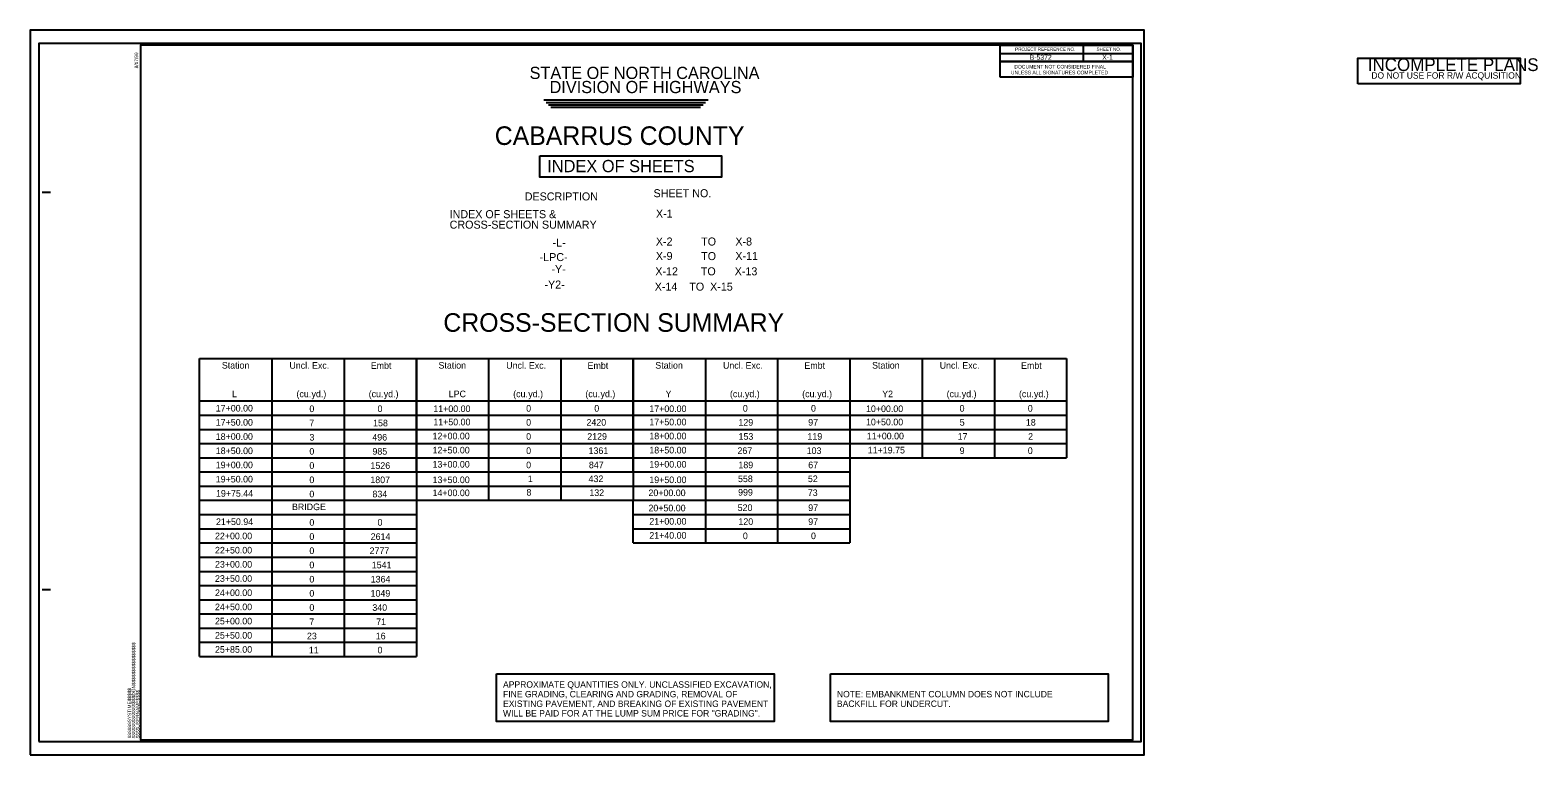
# Model space of a CAD drawing. Extents: x -16215 to -14848, y -1968 to -1311.
import ezdxf

# ---------------------------------------------------------------- set-up
doc = ezdxf.new("R2010")
doc.units = 0
for name, color, linetype in [('Default', 7, 'Continuous'), ('Old_Level_12', 7, 'Continuous'), ('Old_Level_40', 7, 'Continuous'), ('Old_Level_44', 7, 'Continuous'), ('Prop DSN Text', 7, 'Continuous'), ('Sheet Data Field CELL', 7, 'Continuous'), ('Sheet Plan CELL', 7, 'Continuous'), ('Sheet Plot Border Inside CELL', 7, 'Continuous'), ('Sheet Plot Border Outside CELL', 7, 'Continuous'), ('Sheet Sticker Exception Certification CELL', 7, 'Continuous'), ('Sheet Sticker Incomplete CELL', 7, 'Continuous')]:
    doc.layers.add(name, color=color, linetype=linetype)

msp = doc.modelspace()

# ---------------------------------------------------------------- linework, layer by layer
at = {"layer": 'Default'}
for points in [[(-15753.3, -1424.7), (-15588.5, -1424.7), (-15588.5, -1444), (-15753.3, -1443.9)], [(-15792.5, -1894.3), (-15540.6, -1894.3), (-15540.6, -1937.4), (-15792.5, -1937.4)], [(-15489.7, -1894.3), (-15237.8, -1894.3), (-15237.8, -1937.4), (-15489.7, -1937.4)]]:
    msp.add_lwpolyline(points, close=True, dxfattribs=at)
at = {"layer": 'Old_Level_12'}
for p, q in [((-15749.7, -1374), (-15600.6, -1374)), ((-15749.7, -1374), (-15600.6, -1374)), ((-15747.6, -1376.3), (-15602.9, -1376.3)), ((-15745.3, -1378.5), (-15605.2, -1378.5)), ((-15743.1, -1380.7), (-15607.5, -1380.7))]:
    msp.add_line(p, q, dxfattribs=at)
at = {"layer": 'Prop DSN Text'}
for p, q in [((-16061.8, -1608.3), (-15865.2, -1608.3)), ((-16061.8, -1878.6), (-16061.8, -1608.3)), ((-15996.2, -1608.3), (-15996.2, -1711.3)), ((-15930.7, -1608.3), (-15930.7, -1711.3)), ((-15865.2, -1608.3), (-15865.2, -1878.6)), ((-15865.2, -1608.3), (-15668.6, -1608.3)), ((-15865.2, -1711.3), (-15865.2, -1608.3)), ((-15799.7, -1608.3), (-15799.7, -1737)), ((-15734.2, -1608.3), (-15734.2, -1737)), ((-15668.6, -1608.3), (-15668.6, -1737)), ((-15668.6, -1608.3), (-15472.1, -1608.3)), ((-15668.6, -1711.3), (-15668.6, -1608.3)), ((-15603.1, -1608.3), (-15603.1, -1737)), ((-15537.6, -1608.3), (-15537.6, -1737)), ((-15472.1, -1608.3), (-15472.1, -1737)), ((-15472.1, -1608.3), (-15275.5, -1608.3)), ((-15406.6, -1608.3), (-15406.6, -1698.4)), ((-15341, -1608.3), (-15341, -1698.4)), ((-15275.5, -1608.3), (-15275.5, -1698.4)), ((-16061.8, -1646.9), (-15865.2, -1646.9)), ((-15996.2, -1646.6), (-15996.2, -1878.2)), ((-15930.7, -1646.6), (-15930.7, -1878.2)), ((-15865.2, -1646.9), (-15668.6, -1646.9)), ((-15668.6, -1646.9), (-15472.1, -1646.9)), ((-15472.1, -1646.9), (-15275.5, -1646.9)), ((-16061.8, -1659.8), (-15865.2, -1659.8)), ((-15865.2, -1659.8), (-15668.6, -1659.8)), ((-15668.6, -1659.8), (-15472.1, -1659.8)), ((-15472.1, -1659.8), (-15275.5, -1659.8)), ((-16061.8, -1672.7), (-15865.2, -1672.7)), ((-15865.2, -1672.7), (-15668.6, -1672.7)), ((-15668.6, -1672.7), (-15472.1, -1672.7)), ((-15472.1, -1672.7), (-15275.5, -1672.7)), ((-16061.8, -1685.5), (-15865.2, -1685.5)), ((-15865.2, -1685.5), (-15668.6, -1685.5)), ((-15668.6, -1685.5), (-15472.1, -1685.5)), ((-15472.1, -1685.5), (-15275.5, -1685.5)), ((-16061.8, -1698.4), (-15865.2, -1698.4)), ((-15865.2, -1698.4), (-15668.6, -1698.4)), ((-15668.6, -1698.4), (-15472.1, -1698.4)), ((-15472.1, -1698.4), (-15275.5, -1698.4)), ((-16061.8, -1711.3), (-15865.2, -1711.3)), ((-16061.8, -1711.3), (-15865.2, -1711.3)), ((-15996.2, -1710.9), (-15996.2, -1775.3)), ((-15930.7, -1710.9), (-15930.7, -1775.3)), ((-15865.2, -1711.3), (-15668.6, -1711.3)), ((-15865.2, -1711.3), (-15668.6, -1711.3)), ((-15668.6, -1711.3), (-15472.1, -1711.3)), ((-15668.6, -1711.3), (-15472.1, -1711.3)), ((-16061.8, -1724.1), (-15865.2, -1724.1)), ((-15865.2, -1724.1), (-15668.6, -1724.1)), ((-15668.6, -1724.1), (-15472.1, -1724.1)), ((-16061.8, -1737), (-15865.2, -1737)), ((-16061.8, -1749.9), (-15865.2, -1749.9)), ((-15865.2, -1737), (-15668.6, -1737)), ((-15668.6, -1737), (-15472.1, -1737)), ((-15668.6, -1775.6), (-15668.6, -1737)), ((-15668.6, -1749.9), (-15472.1, -1749.9)), ((-15603.1, -1737), (-15603.1, -1775.6)), ((-15537.6, -1737), (-15537.6, -1775.6)), ((-15472.1, -1737), (-15472.1, -1775.6)), ((-16061.8, -1762.8), (-15865.2, -1762.8)), ((-15668.6, -1762.8), (-15472.1, -1762.8)), ((-16061.8, -1775.6), (-15865.2, -1775.6)), ((-16061.8, -1775.6), (-15865.2, -1775.6)), ((-15668.6, -1775.6), (-15472.1, -1775.6)), ((-16061.8, -1788.5), (-15865.2, -1788.5)), ((-16061.8, -1801.4), (-15865.2, -1801.4)), ((-16061.8, -1814.2), (-15865.2, -1814.2)), ((-16061.8, -1827.1), (-15865.2, -1827.1)), ((-16061.8, -1840), (-15865.2, -1840)), ((-16061.8, -1852.8), (-15865.2, -1852.8)), ((-16061.8, -1865.7), (-15865.2, -1865.7)), ((-16061.8, -1878.6), (-15865.2, -1878.6))]:
    msp.add_line(p, q, dxfattribs=at)
at = {"layer": 'Sheet Plan CELL'}
for p, q in [((-16115.5, -1324.2), (-16115.5, -1324.2)), ((-15260.5, -1324.3), (-15260.5, -1339.3)), ((-15335.6, -1331.8), (-15215.5, -1331.8)), ((-15335.6, -1339.3), (-15215.5, -1339.3)), ((-15335.6, -1339.3), (-15215.5, -1339.3)), ((-16204.6, -1457.7), (-16197.1, -1457.7)), ((-16204.6, -1817.7), (-16197.1, -1817.7)), ((-16115.5, -1954.2), (-16115.5, -1954.2))]:
    msp.add_line(p, q, dxfattribs=at)
for points in [[(-15215.5, -1324.2), (-16115.5, -1324.2), (-16115.5, -1954.2), (-15215.5, -1954.2)], [(-15335.6, -1324.2), (-15215.5, -1324.2), (-15215.5, -1339.3), (-15335.6, -1339.3)]]:
    msp.add_lwpolyline(points, close=True, dxfattribs=at)
at = {"layer": 'Sheet Plot Border Inside CELL'}
msp.add_lwpolyline([(-16207.6, -1955.7), (-15208, -1955.7), (-15208, -1322.7), (-16207.6, -1322.7)], close=True, dxfattribs=at)
at = {"layer": 'Sheet Plot Border Outside CELL'}
msp.add_lwpolyline([(-16215.4, -1967.7), (-15205.3, -1967.7), (-15205.3, -1310.7), (-16215.4, -1310.7)], close=True, dxfattribs=at)
at = {"layer": 'Sheet Sticker Exception Certification CELL'}
for p, q in [((-15335.6, -1353.4), (-15335.6, -1339.3)), ((-15335.6, -1339.3), (-15215.5, -1339.3)), ((-15215.5, -1339.3), (-15215.5, -1353.4)), ((-15215.5, -1353.4), (-15335.6, -1353.4))]:
    msp.add_line(p, q, dxfattribs=at)
at = {"layer": 'Sheet Sticker Incomplete CELL'}
msp.add_lwpolyline([(-15011.3, -1359.5), (-15011.3, -1336), (-14864.3, -1336), (-14864.3, -1359.5)], close=True, dxfattribs=at)

# ---------------------------------------------------------------- texts
at = {"layer": 'Default'}
for s, height, p in [('INDEX OF SHEETS', 11.105, (-15746.5, -1439.5)), ('DESCRIPTION', 7.267, (-15766.9, -1465.1)), ('SHEET NO.', 7.27, (-15650.1, -1462.2))]:
    msp.add_text(s, height=height, rotation=359.992, dxfattribs=at).set_placement(p)
for s, height, p in [('INDEX OF SHEETS &', 7.267, (-15835, -1481.2)), ('X-1', 7.27, (-15647.9, -1480.7)), ('CROSS-SECTION SUMMARY', 7.267, (-15835, -1490.7)), ('-L-', 7.27, (-15741.6, -1507)), ('X-2', 7.27, (-15648, -1506)), ('TO', 7.27, (-15606.9, -1506)), ('X-8', 7.27, (-15575.9, -1506)), ('-LPC-', 7.27, (-15753.4, -1520.1)), ('X-9', 7.27, (-15648, -1519.1)), ('TO', 7.27, (-15606.9, -1519.2)), ('X-11', 7.27, (-15575.9, -1519.1)), ('-Y-', 7.27, (-15742.7, -1531)), ('X-12', 7.27, (-15648.5, -1533)), ('TO', 7.27, (-15607.2, -1533)), ('X-13', 7.27, (-15576.5, -1533)), ('-Y2-', 7.27, (-15749, -1545)), ('X-14    TO  X-15', 7.267, (-15649, -1546.9)), ('APPROXIMATE QUANTITIES ONLY. UNCLASSIFIED EXCAVATION,', 5.814, (-15786.6, -1906.9)), ('FINE GRADING, CLEARING AND GRADING, REMOVAL OF ', 5.814, (-15786.6, -1915.6)), ('NOTE: EMBANKMENT COLUMN DOES NOT INCLUDE ', 5.814, (-15483.8, -1915.6)), ('WILL BE PAID FOR AT THE LUMP SUM PRICE FOR "GRADING".', 5.814, (-15786.6, -1933)), ('EXISTING PAVEMENT, AND BREAKING OF EXISTING PAVEMENT', 5.814, (-15786.6, -1924.3)), ('BACKFILL FOR UNDERCUT.', 5.814, (-15483.8, -1924.3))]:
    msp.add_text(s, height=height, dxfattribs=at).set_placement(p)
at = {"layer": 'Old_Level_40'}
for s, p in [('CABARRUS COUNTY', (-15794.1, -1414.8)), ('CROSS-SECTION SUMMARY', (-15840.7, -1584.2))]:
    msp.add_text(s, height=16.841, rotation=359.9982, dxfattribs=at).set_placement(p)
at = {"layer": 'Old_Level_44'}
for s, p in [('STATE OF NORTH CAROLINA', (-15762.5, -1355)), ('DIVISION OF HIGHWAYS', (-15744.4, -1367.8))]:
    msp.add_text(s, height=11.049, rotation=359.9915, dxfattribs=at).set_placement(p)
at = {"layer": 'Prop DSN Text'}
for s, p in [('Station', (-16041.6, -1617.6)), ('Uncl. Exc.', (-15980.3, -1617.7)), ('Embt', (-15906.5, -1617.8)), ('Station', (-15845.1, -1617.6)), ('Uncl. Exc.', (-15783.7, -1617.7)), ('Embt', (-15709.9, -1617.8)), ('Station', (-15648.5, -1617.6)), ('Uncl. Exc.', (-15587.1, -1617.7)), ('Embt', (-15513.3, -1617.8)), ('Station', (-15451.9, -1617.6)), ('Uncl. Exc.', (-15390.6, -1617.7)), ('Embt', (-15316.8, -1617.8)), ('L', (-16032.3, -1643.5)), ('(cu.', (-15973.9, -1643.5)), (' yd.)', (-15962.5, -1643.5)), ('(cu.', (-15908.4, -1643.5)), (' yd.)', (-15897, -1643.5)), ('LPC', (-15835.8, -1643.5)), ('(cu.', (-15777.4, -1643.5)), (' yd.)', (-15765.9, -1643.5)), ('(cu.', (-15711.9, -1643.5)), (' yd.)', (-15700.4, -1643.5)), ('Y', (-15639.2, -1643.5)), ('(cu.', (-15580.8, -1643.5)), (' yd.)', (-15569.4, -1643.5)), ('(cu.', (-15515.3, -1643.5)), (' yd.)', (-15503.8, -1643.5)), ('Y2', (-15442.7, -1643.5)), ('(cu.', (-15384.3, -1643.5)), (' yd.)', (-15372.8, -1643.5)), ('(cu.', (-15318.7, -1643.5)), (' yd.)', (-15307.3, -1643.5)), ('17+00.00', (-16047.1, -1656.5)), ('0', (-15962.2, -1657)), ('0', (-15900.4, -1657)), ('11+00.00', (-15849.8, -1657)), ('0', (-15765.6, -1656.6)), ('0', (-15703.8, -1656.6)), ('17+00.00', (-15653.9, -1657)), ('0', (-15569.1, -1656.6)), ('0', (-15507.3, -1656.6)), ('10+00.00', (-15457.4, -1657)), ('0', (-15372.5, -1656.6)), ('0', (-15310.7, -1656.6)), ('17+50.00', (-16047.1, -1669.3)), ('7', (-15962.3, -1669.9)), ('158', (-15904.4, -1669.9)), ('11+50.00', (-15849.8, -1669)), ('0', (-15765.6, -1669.3)), ('2420', (-15710.9, -1669.3)), ('17+50.00', (-15653.9, -1669)), ('129', (-15573.1, -1669.3)), ('97', (-15509.8, -1669.3)), ('10+50.00', (-15457.4, -1669)), ('5', (-15372.4, -1669.3)), ('18', (-15312.4, -1669.3)), ('18+00.00', (-16047.1, -1682.2)), ('3', (-15962.1, -1682.8)), ('496', (-15905.1, -1682.8)), ('12+00.00', (-15850.5, -1681.7)), ('0', (-15765.6, -1682.1)), ('2129', (-15710.2, -1682.1)), ('18+00.00', (-15653.9, -1681.7)), ('153', (-15573, -1682.1)), ('119', (-15510.5, -1682.1)), ('11+00.00', (-15456.7, -1681.7)), ('17', (-15374.3, -1682.1)), ('2', (-15310.4, -1682.1)), ('18+50.00', (-16047.1, -1695.1)), ('0', (-15962.2, -1695.6)), ('985', (-15905, -1695.6)), ('12+50.00', (-15850.5, -1694.5)), ('0', (-15765.6, -1695)), ('1361', (-15709, -1695)), ('18+50.00', (-15653.9, -1694.5)), ('267', (-15574, -1695)), ('103', (-15511.2, -1695)), ('11+19.75', (-15455.8, -1694.5)), ('9', (-15372.5, -1695)), ('0', (-15310.7, -1695)), ('19+00.00', (-16047.1, -1707.9)), ('0', (-15962.2, -1708.5)), ('1526', (-15906.8, -1708.5)), ('13+00.00', (-15850.5, -1707.3)), ('0', (-15765.6, -1707.9)), ('847', (-15708.7, -1707.9)), ('19+00.00', (-15653.9, -1707.3)), ('189', (-15573.1, -1707.9)), ('67', (-15509.8, -1707.9)), ('19+50.00', (-16047.1, -1720.8)), ('0', (-15962.2, -1721.4)), ('1807', (-15906.9, -1721.4)), ('13+50.00', (-15850.5, -1721.4)), ('1', (-15764.1, -1720.5)), ('432', (-15709, -1720.5)), ('19+50.00', (-15653.9, -1721.4)), ('558', (-15573.5, -1720.5)), ('52', (-15510.1, -1720.5)), ('19+75.44', (-16046.9, -1733.7)), ('0', (-15962.2, -1734.3)), ('834', (-15905, -1734.3)), ('14+00.00', (-15850.5, -1733.2)), ('8', (-15765.3, -1732.7)), ('132', (-15708.3, -1733.1)), ('20+00.00', (-15654.7, -1733.2)), ('999', (-15573.4, -1732.7)), ('73', (-15510.2, -1733.1)), ('BRIDGE', (-15978, -1745.9)), ('20+50.00', (-15654.7, -1747)), ('520', (-15573.8, -1746.7)), ('97', (-15509.8, -1746.7)), ('21+50.94', (-16046.9, -1759.4)), ('0', (-15962.2, -1760)), ('0', (-15900.4, -1760)), ('21+00.00', (-15653.9, -1759)), ('120', (-15573.1, -1759.3)), ('97', (-15509.8, -1759.3)), ('22+00.00', (-16047.8, -1772.3)), ('0', (-15962.2, -1772.9)), ('2614', (-15906.6, -1772.9)), ('21+40.00', (-15653.9, -1771.8)), ('0', (-15569.1, -1772.2)), ('0', (-15507.3, -1772.2)), ('22+50.00', (-16047.8, -1785.2)), ('0', (-15962.2, -1785.7)), ('2777', (-15907.6, -1785.7)), ('23+00.00', (-16047.8, -1798)), ('23+50.00', (-16047.8, -1810.9)), ('0', (-15962.2, -1798.6)), ('1541', (-15905.6, -1798.6)), ('24+00.00', (-16047.8, -1823.8)), ('0', (-15962.2, -1811.5)), ('0', (-15962.2, -1824.3)), ('1049', (-15906.7, -1824.3)), ('1364', (-15906.6, -1811.5)), ('24+50.00', (-16047.8, -1836.6)), ('0', (-15962.2, -1837.2)), ('340', (-15905.1, -1837.2)), ('25+00.00', (-16047.8, -1849.5)), ('7', (-15962.3, -1850.1)), ('71', (-15901.6, -1850.1)), ('25+50.00', (-16047.8, -1862.4)), ('23', (-15964.4, -1863)), ('16', (-15902, -1863)), ('25+85.00', (-16047.8, -1875.2)), ('11', (-15962.7, -1875.8)), ('0', (-15900.4, -1875.8))]:
    msp.add_text(s, height=6, dxfattribs=at).set_placement(p)
at = {"layer": 'Sheet Data Field CELL'}
for s, p in [('B-5372', (-15309, -1337.6)), ('X-1', (-15243.2, -1337.6))]:
    msp.add_text(s, height=4.5, dxfattribs=at).set_placement(p)
at = {"layer": 'Sheet Plan CELL'}
for s, p in [('8/17/99', (-16117.5, -1345.4)), ('$$$$$$$$$$$$$$$$DGN$$$$$$$$$$$$$$$$', (-16120.1, -1952.8)), ('$$$$$$SYSTIME$$$$$', (-16123.8, -1952.8)), ('$$$$USERNAME$$$$', (-16116.2, -1952.8))]:
    msp.add_text(s, height=3.15, rotation=90, dxfattribs=at).set_placement(p)
for s, p in [('PROJECT REFERENCE NO.', (-15322.2, -1329.5)), ('SHEET NO.', (-15248.4, -1329.5))]:
    msp.add_text(s, height=3, dxfattribs=at).set_placement(p)
at = {"layer": 'Sheet Sticker Exception Certification CELL'}
for s, p in [('UNLESS ALL SIGNATURES COMPLETED', (-15326, -1350.8)), ('DOCUMENT NOT CONSIDERED FINAL', (-15322.9, -1345.5))]:
    msp.add_text(s, height=3.3, dxfattribs=at).set_placement(p)
at = {"layer": 'Sheet Sticker Incomplete CELL'}
for s, height, p in [('INCOMPLETE PLANS', 11.52, (-15002.4, -1347.8)), ('DO NOT USE FOR R/W ACQUISITION', 5.76, (-14999.1, -1354.7))]:
    msp.add_text(s, height=height, dxfattribs=at).set_placement(p)

doc.saveas('drawing.dxf')
